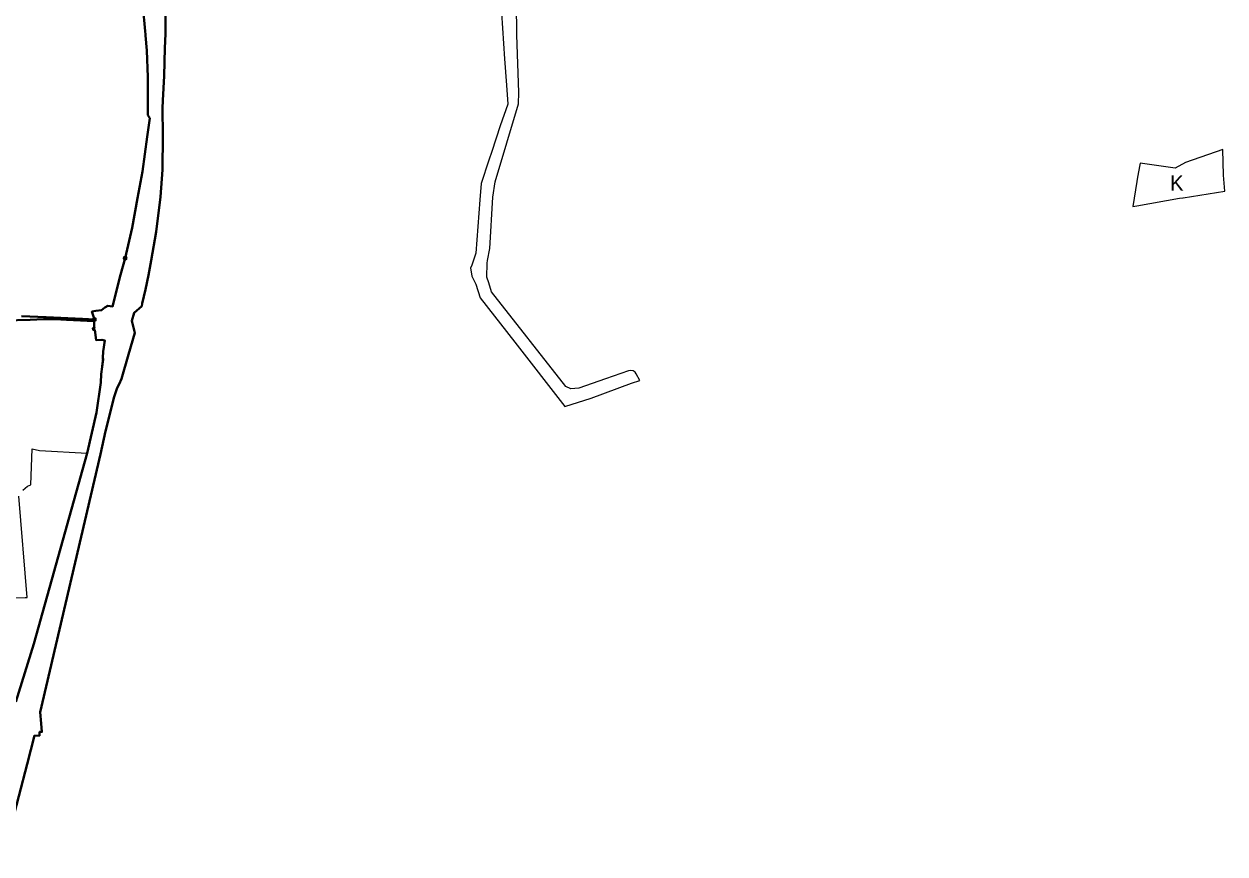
# Model space of a CAD drawing. Extents: x -650276 to -642489, y -1074311 to -1066658.
# Drawn here: x -645192 to -643315, y -1071606 to -1070308 of the extents above; entities that cross this region are included whole.
import ezdxf

# ---------------------------------------------------------------- set-up
doc = ezdxf.new("R2010")
doc.units = 0
doc.header["$LTSCALE"] = 9.6
doc.header["$PDMODE"] = 32
doc.header["$PDSIZE"] = 4.8
for name, color, linetype, lineweight in [('44', 7, 'Continuous', 40), ('47', 7, 'Continuous', 13), ('48', 7, 'Continuous', 13)]:
    doc.layers.add(name, color=color, linetype=linetype, lineweight=lineweight)

msp = doc.modelspace()

# ---------------------------------------------------------------- linework, layer by layer
at = {"layer": '44'}
for points in [[(-645166.34, -1071384.07), (-645071.99, -1070980.72), (-645064.39, -1070944.7), (-645050.47, -1070891.48), (-645045.74, -1070877.19), (-645043, -1070871.35), (-645039.25, -1070863.33), (-645028.25, -1070824.83), (-645018.18, -1070791.34), (-645023.25, -1070772.62), (-645019.57, -1070760.07), (-645007.68, -1070749.5), (-645006.739, -1070745.384), (-645001.71, -1070723.39), (-644997.14, -1070700.88), (-644992.6, -1070677.92), (-644985.04, -1070633.43), (-644978.44, -1070578.56), (-644975.05, -1070536.16), (-644974.44, -1070482.48), (-644975.29, -1070440.14), (-644974.69, -1070427.86), (-644972.48, -1070389.15), (-644971.37, -1070345.98), (-644970.61, -1070323.44), (-644970.55, -1070321.56), (-644970.524, -1070315.358), (-644970.36, -1070275.49)], [(-645005.98, -1070280.14), (-645002.308, -1070319.268), (-645001.81, -1070324.58), (-645001.64, -1070326.4)], [(-645001.64, -1070326.4), (-644999.47, -1070349.63), (-644997.87, -1070391.16), (-644998.25, -1070430.5), (-644998.17, -1070450.59), (-644995.14, -1070455.72), (-644998.92, -1070484.58), (-645006.44, -1070538.78), (-645014.07, -1070580.72), (-645022.64, -1070626.93), (-645033.53, -1070674.55)], [(-645033.53, -1070674.55), (-645041, -1070700.44), (-645046.63, -1070722.77), (-645052.4, -1070746.427), (-645053.21, -1070749.75), (-645060.46, -1070749.1), (-645065.17, -1070751.39), (-645070.3, -1070755.92), (-645079.38, -1070756.91), (-645085.58, -1070758.04), (-645081.6, -1070770.362)], [(-645195.527, -1070765.319), (-645156.988, -1070766.884), (-645100.32, -1070769.5), (-645081.6, -1070770.362), (-645081.75, -1070772.79), (-645125.217, -1070770.81), (-645143, -1070770), (-645161, -1070770), (-645182, -1070771), (-645303, -1070774)], [(-645081.6, -1070770.362), (-645081.75, -1070772.79), (-645081.85, -1070781.59), (-645081.57, -1070783.53), (-645083.95, -1070783.89), (-645083.49, -1070786.92), (-645081.13, -1070786.56), (-645078.85, -1070802.46), (-645070.2, -1070802.33), (-645065.01, -1070803.22), (-645068.07, -1070820.37)], [(-645068.07, -1070820.37), (-645068.52, -1070830.52), (-645068.07, -1070832.72), (-645071.18, -1070855.63), (-645071.77, -1070868.73), (-645078.23, -1070915.65)], [(-645078.23, -1070915.65), (-645092.67, -1070979.52), (-645176.14, -1071277.26), (-645204.341, -1071368.19)], [(-645222.48, -1071606.08), (-645211.27, -1071560.01), (-645199.61, -1071515.68), (-645186.67, -1071465.55), (-645175.06, -1071420.93), (-645167.58, -1071421.19), (-645167.37, -1071415.2), (-645163.56, -1071415.3), (-645164.76, -1071401.79), (-645166.34, -1071384.07)]]:
    msp.add_lwpolyline(points, dxfattribs=at)
for p in [(-645033.53, -1070674.55), (-645081.6, -1070770.362)]:
    msp.add_point(p, dxfattribs=at)
at = {"layer": '47'}
for points in [[(-644243.15, -1070849.89), (-644246.93, -1070850.52), (-644282.77, -1070863.19), (-644324.34, -1070877.71), (-644337.15, -1070878.64), (-644344.86, -1070875.09), (-644460.82, -1070727.21), (-644465.31, -1070713.25), (-644468.1, -1070704.23), (-644467.84, -1070682.37), (-644466.998, -1070678.065), (-644463.28, -1070659.06), (-644458.85, -1070579.04), (-644455.2, -1070554.88), (-644418.69, -1070433.36), (-644418.23, -1070415.62), (-644421.45, -1070325.29), (-644422.5, -1070226.42), (-644420.14, -1070208.56), (-644418.61, -1070204.51), (-644417.36, -1070203.24), (-644407.55, -1070194.16), (-644399.15, -1070188.55)], [(-644445.28, -1070290.84), (-644440.36, -1070362.62), (-644437.53, -1070404.1), (-644435.51, -1070433.85), (-644447.14, -1070467.28), (-644460.5, -1070507.68), (-644464.98, -1070521.13), (-644476.94, -1070557.45), (-644479.06, -1070583.13), (-644485.64, -1070666.7), (-644488.01, -1070674.2), (-644491.691, -1070685.524), (-644491.82, -1070685.92), (-644493.5, -1070689.75), (-644491.42, -1070702.64), (-644485.61, -1070714.95), (-644478.67, -1070736.28), (-644424.37, -1070806.03), (-644346.21, -1070906.61), (-644305.07, -1070893.39), (-644242.29, -1070869.82), (-644229.12, -1070865.52), (-644234.66, -1070855.08), (-644236.3, -1070852.87), (-644239.47, -1070850.71), (-644243.15, -1070849.89)], [(-643452.22, -1070592.35), (-643385.72, -1070580.86), (-643380.35, -1070580.14), (-643380.08, -1070580.09), (-643314.51, -1070569.69), (-643315.27, -1070563.2), (-643317.08, -1070544.75), (-643317.9, -1070504.73)], [(-643317.9, -1070504.73), (-643376.07, -1070524.59), (-643392.41, -1070533.68), (-643446.89, -1070526.01)], [(-643446.89, -1070526.01), (-643447.79, -1070528.63), (-643450.98, -1070547.74), (-643452.14, -1070554.77)], [(-643452.14, -1070554.77), (-643458.42, -1070593.43), (-643452.22, -1070592.35)], [(-645193.24, -1071037.31), (-645186.18, -1071030.83), (-645180.72, -1071028.86), (-645178.73, -1070972.35), (-645167.47, -1070975.2), (-645092.67, -1070979.52), (-645090.464, -1070969.761), (-645078.23, -1070915.65), (-645076.052, -1070899.832), (-645072.44, -1070873.596), (-645070.222, -1070848.57), (-645065.01, -1070803.22), (-645078.85, -1070802.46), (-645082.31, -1070770.329), (-645100.268, -1070771.946), (-645143, -1070770), (-645161, -1070770), (-645182, -1070771), (-645194.206, -1070771.303)], [(-645262.13, -1071205.432), (-645189.902, -1071204.885), (-645186.64, -1071204.86), (-645199.57, -1071046.58)]]:
    msp.add_lwpolyline(points, dxfattribs=at)

# ---------------------------------------------------------------- texts
at = {"layer": '48'}
msp.add_text('K', height=24, dxfattribs=at).set_placement((-643400.597, -1070568.968))
msp.add_text('K', height=24, dxfattribs=at).set_placement((-643400.597, -1070568.968))

doc.saveas('drawing.dxf')
